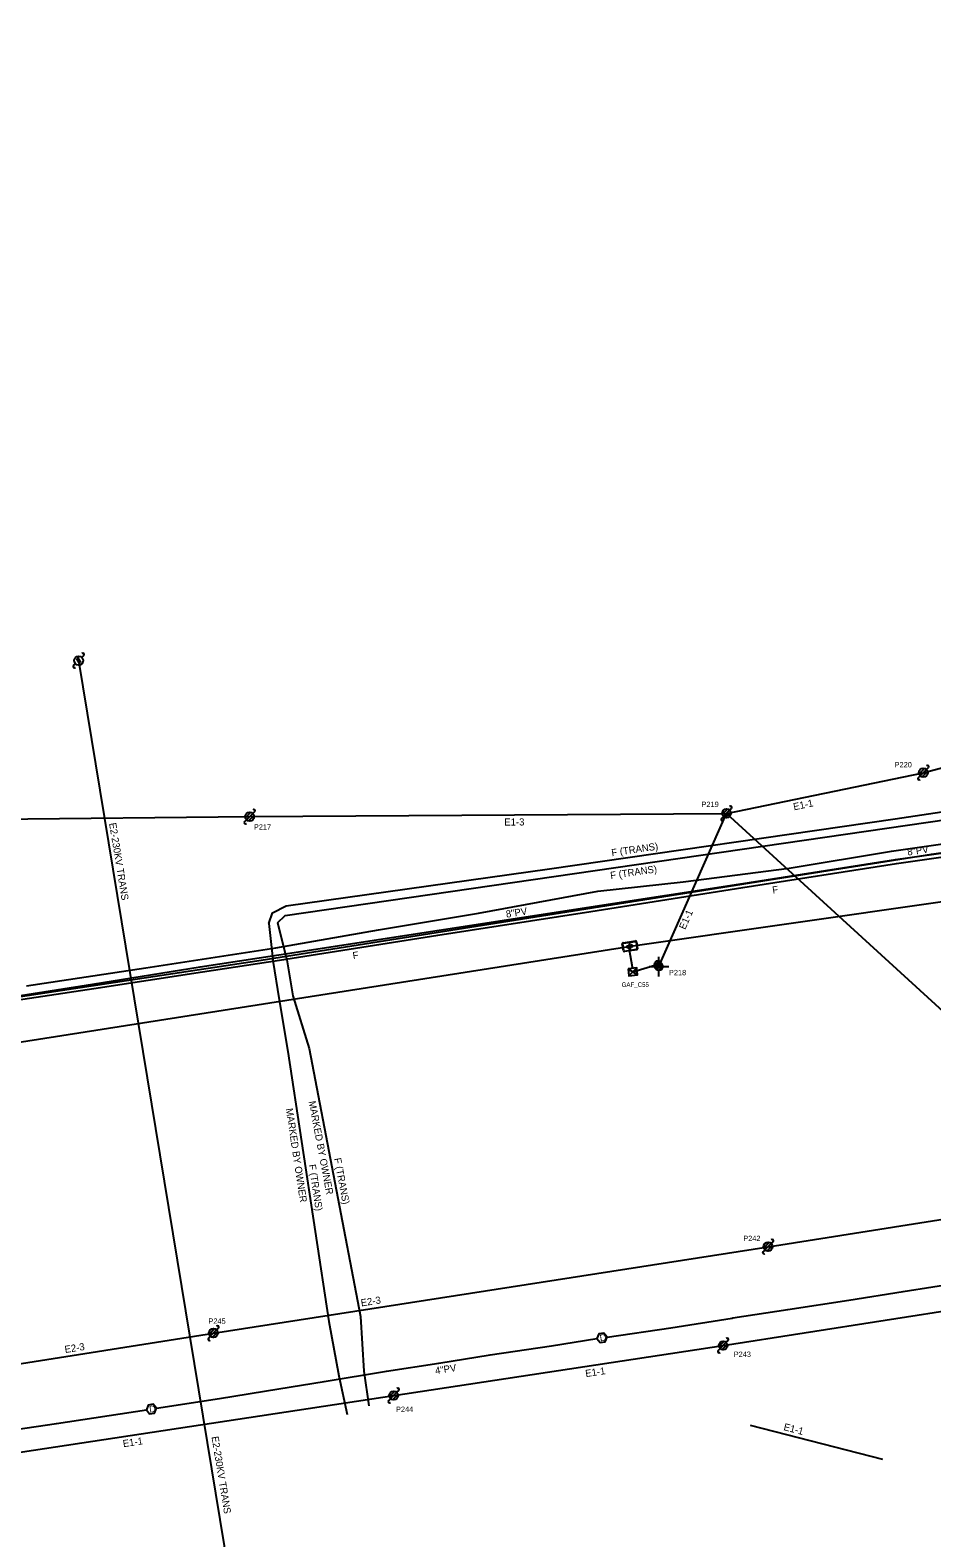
# Model space of a CAD drawing. Extents: x 1614474 to 1865144, y 1098877 to 1212550.
# Drawn here: x 1775781 to 1776287, y 1179752 to 1180599 of the extents above; entities that cross this region are included whole.
import ezdxf

# ---------------------------------------------------------------- set-up
doc = ezdxf.new("R2010")
doc.units = 0
for name, color, linetype in [('BFUSER_CABINET', 7, 'Continuous'), ('BFUSER_DUCTENCLOSURE', 7, 'Continuous'), ('BFUSER_FIBERNODE', 7, 'Continuous'), ('BFUSER_FIBERNODENAME', 7, 'Continuous'), ('BFUSER_FIBERSPAN', 7, 'Continuous'), ('BFUSER_FIBERSPLICEENCLOSURE', 7, 'Continuous'), ('RD_EX_SU_Elec', 7, 'Continuous'), ('RD_EX_SU_H2O', 7, 'Continuous'), ('RD_EX_SU_Ovhd', 7, 'Continuous'), ('RD_EX_SU_Pole', 7, 'Continuous'), ('RD_EX_SU_Telecom', 7, 'Continuous'), ('RD_EX_SU_TX_H2O', 7, 'Continuous'), ('RD_EX_SU_TX_Pole', 7, 'Continuous'), ('RD_EX_SU_TX_Telecom', 7, 'Continuous')]:
    doc.layers.add(name, color=color, linetype=linetype)

# ---------------------------------------------------------------- blocks, each defined once
blk = doc.blocks.new('SUE_PLT')
at = {"layer": 'RD_EX_SU_Elec'}
for p, q in [((1.77, 1.77), (2.83, 2.83)), ((-2.83, -2.83), (-1.77, -1.77))]:
    blk.add_line(p, q, dxfattribs=at)
blk.add_lwpolyline([(-0.49, 1.95), (0.34, -0.06), (-1.12, 0.74), (0.75, -1.95), (0.75, -1.95), (-0.45, 0.15), (0.94, -0.65)], close=True, dxfattribs=at)
blk.add_circle((0, 0), 2.5, dxfattribs=at)
for centre, start, end in [((2.3, 3.36), 315, 135), ((-2.3, -3.36), 135, 315)]:
    blk.add_arc(centre, 0.75, start, end, dxfattribs=at)

msp = doc.modelspace()

# ---------------------------------------------------------------- linework, layer by layer
at = {"layer": 'BFUSER_CABINET'}
for p, q in [((1776116.61, 1180071.7), (1776121.95, 1180068.18)), ((1776121.58, 1180072.16), (1776116.97, 1180067.72))]:
    msp.add_line(p, q, dxfattribs=at)
msp.add_lwpolyline([(1776116.61, 1180071.7), (1776116.97, 1180067.72), (1776121.95, 1180068.18), (1776121.58, 1180072.16)], close=True, dxfattribs=at)
at = {"layer": 'BFUSER_DUCTENCLOSURE'}
msp.add_line((1776117.32, 1180086.55), (1776117.98, 1180082.09), dxfattribs=at)
for points in [[(1776113.98, 1180081.75), (1776113.4, 1180085.71)], [(1776114.19, 1180081.93), (1776113.65, 1180085.6)], [(1776113.82, 1180086.28), (1776120.75, 1180087.3)], [(1776113.99, 1180086.05), (1776120.65, 1180087.04)], [(1776121.1, 1180086.7), (1776121.65, 1180083.03)], [(1776121.31, 1180086.88), (1776121.9, 1180082.92)], [(1776121.48, 1180082.36), (1776114.55, 1180081.33)], [(1776114.65, 1180081.6), (1776121.31, 1180082.58)]]:
    msp.add_lwpolyline(points, dxfattribs=at)
for centre, radius, start, end in [((1776113.89, 1180085.78), 0.5, 98.4061, 188.4061), ((1776114.05, 1180085.66), 0.4, 98.4061, 188.4061), ((1776120.71, 1180086.64), 0.4, 8.4061, 98.4061), ((1776120.82, 1180086.81), 0.5, 8.4061, 98.4061), ((1776114.48, 1180081.83), 0.5, 188.4061, 278.4061), ((1776114.59, 1180081.99), 0.4, 188.4061, 278.4061), ((1776121.25, 1180082.98), 0.4, 278.4061, 8.4061), ((1776121.4, 1180082.85), 0.5, 278.4061, 8.4061)]:
    msp.add_arc(centre, radius, start, end, dxfattribs=at)
at = {"layer": 'BFUSER_FIBERNODE'}
msp.add_line((1776131.53, 1180073.61), (1776135.36, 1180074.75), dxfattribs=at)
msp.add_lwpolyline([(1776132.68, 1180073.95), (1776134.26, 1180074.42), (1776134.46, 1180073.74), (1776132.89, 1180073.27)], close=True, dxfattribs=at)
msp.add_circle((1776133.44, 1180074.18), 2, dxfattribs=at)
msp.add_arc((1776133.52, 1180074.03), 0.992, 230.51607, 342.80602, dxfattribs=at)
at = {"layer": 'BFUSER_FIBERSPAN'}
for p, q in [((1776117.12, 1180083.43), (1776119.12, 1180071.68)), ((1776119.28, 1180069.94), (1776133.47, 1180074.19))]:
    msp.add_line(p, q, dxfattribs=at)
for points in [[(1776119.38, 1180084.52), (1776909.44, 1180197.58), (1777549.89, 1180288.26), (1777793.65, 1180334.21), (1778099.34, 1180399.49), (1778312.74, 1180438.72), (1779456.83, 1180598.99)], [(1772266.13, 1179233.73), (1772993.33, 1179552.36), (1773074.83, 1179562.18), (1773346.25, 1179631.55), (1773610.67, 1179692.14), (1774668.73, 1179856.77), (1776115.67, 1180083.91)]]:
    msp.add_lwpolyline(points, dxfattribs=at)
at = {"layer": 'BFUSER_FIBERSPLICEENCLOSURE'}
for p, q in [((1776115.81, 1180084.23), (1776115.82, 1180084.23)), ((1776115.83, 1180084.1), (1776115.81, 1180084.23)), ((1776115.82, 1180084.25), (1776116.17, 1180084.32)), ((1776115.85, 1180084.09), (1776115.82, 1180084.25)), ((1776115.82, 1180084.23), (1776115.85, 1180084.11)), ((1776116.39, 1180083.43), (1776116.16, 1180084.5)), ((1776116.16, 1180084.47), (1776116.27, 1180084.5)), ((1776116.39, 1180083.44), (1776116.16, 1180084.47)), ((1776116.23, 1180084.65), (1776116.39, 1180084.69)), ((1776116.52, 1180083.35), (1776116.23, 1180084.65)), ((1776116.27, 1180084.5), (1776116.5, 1180083.47)), ((1776116.39, 1180084.69), (1776116.68, 1180083.38)), ((1776116.41, 1180084.58), (1776118.54, 1180085.05)), ((1776116.43, 1180084.52), (1776118.56, 1180084.98)), ((1776116.81, 1180084.76), (1776116.78, 1180084.76)), ((1776116.78, 1180084.76), (1776116.8, 1180084.67)), ((1776116.8, 1180084.67), (1776116.83, 1180084.67)), ((1776116.83, 1180084.67), (1776116.81, 1180084.76)), ((1776117.12, 1180084.83), (1776117.09, 1180084.83)), ((1776117.09, 1180084.83), (1776117.11, 1180084.74)), ((1776117.11, 1180084.74), (1776117.14, 1180084.74)), ((1776117.14, 1180084.74), (1776117.12, 1180084.83)), ((1776117.91, 1180085.01), (1776117.88, 1180085)), ((1776117.88, 1180085), (1776117.9, 1180084.91)), ((1776117.9, 1180084.91), (1776117.93, 1180084.92)), ((1776117.93, 1180084.92), (1776117.91, 1180085.01)), ((1776118.22, 1180085.07), (1776118.19, 1180085.07)), ((1776118.19, 1180085.07), (1776118.21, 1180084.98)), ((1776118.21, 1180084.98), (1776118.24, 1180084.99)), ((1776118.24, 1180084.99), (1776118.22, 1180085.07)), ((1776118.56, 1180084.98), (1776118.58, 1180084.86)), ((1776118.62, 1180085), (1776118.65, 1180084.87)), ((1776118.74, 1180084.82), (1776118.95, 1180084.87)), ((1776118.75, 1180084.75), (1776118.97, 1180084.8)), ((1776118.97, 1180084.8), (1776119.12, 1180084.1)), ((1776119.04, 1180084.81), (1776119.19, 1180084.12)), ((1776115.85, 1180084.11), (1776115.83, 1180084.1)), ((1776116.2, 1180084.17), (1776115.85, 1180084.09)), ((1776115.85, 1180084.01), (1776115.87, 1180084.02)), ((1776115.88, 1180083.89), (1776115.85, 1180084.01)), ((1776115.86, 1180084.03), (1776116.22, 1180084.11)), ((1776115.9, 1180083.88), (1776115.86, 1180084.03)), ((1776115.87, 1180084.02), (1776115.89, 1180083.89)), ((1776115.89, 1180083.89), (1776115.88, 1180083.89)), ((1776115.89, 1180083.82), (1776115.91, 1180083.82)), ((1776115.98, 1180083.43), (1776115.89, 1180083.82)), ((1776116.25, 1180083.95), (1776115.9, 1180083.88)), ((1776115.9, 1180083.84), (1776116.25, 1180083.92)), ((1776116, 1180083.42), (1776115.9, 1180083.84)), ((1776115.91, 1180083.82), (1776115.99, 1180083.44)), ((1776115.99, 1180083.44), (1776115.98, 1180083.43)), ((1776116.35, 1180083.5), (1776116, 1180083.42)), ((1776116.19, 1180084.16), (1776116.2, 1180084.11)), ((1776116.24, 1180083.95), (1776116.38, 1180083.49)), ((1776116.5, 1180083.47), (1776116.39, 1180083.44)), ((1776116.68, 1180083.38), (1776116.52, 1180083.35)), ((1776119.12, 1180084.1), (1776116.64, 1180083.56)), ((1776119.14, 1180084.04), (1776116.66, 1180083.49))]:
    msp.add_line(p, q, dxfattribs=at)
for centre, radius, start, end in [((1776116.16, 1180084.35), 0.0265, 282.42738, 13.11766), ((1776118.56, 1180084.98), 0.0694, 12.42738, 102.42738), ((1776118.72, 1180084.89), 0.139, 192.42738, 282.42738), ((1776118.66, 1180084.63), 0.42, 31.30954, 99.43431), ((1776118.66, 1180084.63), 0.392, 37.4733, 96.38511), ((1776118.72, 1180084.89), 0.0694, 192.42738, 282.42738), ((1776118.97, 1180084.8), 0.0694, 12.37903, 102.42738), ((1776118.35, 1180084.3), 0.857, 344.43794, 37.27065), ((1776116.21, 1180084.14), 0.0265, 11.73711, 102.42738), ((1776116.21, 1180084.14), 0.0265, 282.42738, 13.11766), ((1776116.26, 1180083.93), 0.0265, 11.73711, 102.42738), ((1776116.36, 1180083.47), 0.0265, 11.73711, 102.42738), ((1776119.12, 1180084.1), 0.0694, 282.42738, 12.37903)]:
    msp.add_arc(centre, radius, start, end, dxfattribs=at)
at = {"layer": 'RD_EX_SU_H2O'}
for points in [[(1775079.31, 1179947.86), (1775099.56, 1179951.26), (1775135.1, 1179956.75), (1775200.12, 1179966.22), (1775230.46, 1179971.15), (1775265.28, 1179976.78), (1775296.44, 1179981.42), (1775327.06, 1179986.33), (1775627.47, 1180033.75), (1775910.53, 1180076.48), (1776287.14, 1180136.1), (1776361.29, 1180146.68), (1776578.76, 1180172.75), (1776784.59, 1180199.86), (1777026.8, 1180236.7)], [(1776104.82, 1179864.77), (1776140.68, 1179869.96), (1776175.04, 1179875.44), (1776175.54, 1179875.52), (1776206.34, 1179880.25), (1776240.64, 1179885.5), (1776271.17, 1179890.42), (1776304.63, 1179895.52), (1776336.21, 1179900.32), (1776336.32, 1179900.34)], [(1775851.67, 1179824.72), (1775887.03, 1179830.27), (1775920.48, 1179835.6), (1775945.8, 1179839.86), (1775980.95, 1179845.52), (1776010.25, 1179850.15), (1776039.23, 1179854.67), (1776073.67, 1179859.88), (1776099.12, 1179863.88)], [(1775632.38, 1179793.92), (1775636.25, 1179794.39), (1775650.79, 1179796.27), (1775680.62, 1179800.13), (1775721.45, 1179805.64), (1775756.05, 1179810.32), (1775795.55, 1179816.27), (1775845.96, 1179823.86)]]:
    msp.add_lwpolyline(points, dxfattribs=at)
for points in [[(1776104.82, 1179864.77), (1776103.01, 1179867.02), (1776100.16, 1179866.57), (1776099.12, 1179863.88), (1776100.93, 1179861.63), (1776103.79, 1179862.08)], [(1775851.67, 1179824.72), (1775849.87, 1179826.98), (1775847.02, 1179826.55), (1775845.96, 1179823.86), (1775847.76, 1179821.6), (1775850.62, 1179822.03)]]:
    msp.add_lwpolyline(points, close=True, dxfattribs=at)
at = {"layer": 'RD_EX_SU_Ovhd'}
for p, q in [((1775807.93, 1180244.81), (1775904.8, 1179655.02)), ((1776282.53, 1180181.83), (1776334.27, 1180195.67)), ((1776171.93, 1180158.93), (1776282.53, 1180181.83)), ((1775583.33, 1180154.06), (1775904.05, 1180157.14)), ((1775904.05, 1180157.14), (1776171.93, 1180158.93)), ((1776133.99, 1180072.92), (1776171.93, 1180158.93)), ((1776171.93, 1180158.93), (1776450.84, 1179903.93)), ((1776195.31, 1179915.49), (1776443.07, 1179954.72)), ((1775883.66, 1179866.98), (1776195.31, 1179915.49)), ((1776170.06, 1179860.01), (1776450.84, 1179903.93)), ((1775717.12, 1179840.5), (1775883.66, 1179866.98)), ((1775984.96, 1179831.92), (1776170.06, 1179860.01)), ((1775716.35, 1179791.24), (1775984.96, 1179831.92)), ((1776185.21, 1179815.22), (1776259.66, 1179796.06))]:
    msp.add_line(p, q, dxfattribs=at)
at = {"layer": 'RD_EX_SU_Pole'}
for p, q in [((1776279.7, 1180179.01), (1776280.77, 1180180.07)), ((1776280.12, 1180181.19), (1776283.18, 1180184.25)), ((1776280.77, 1180180.07), (1776284.3, 1180183.6)), ((1776281.89, 1180179.42), (1776284.95, 1180182.48)), ((1776284.3, 1180183.6), (1776285.36, 1180184.66)), ((1776169.51, 1180158.28), (1776172.57, 1180161.34)), ((1776170.16, 1180157.16), (1776173.69, 1180160.7)), ((1776173.69, 1180160.7), (1776174.75, 1180161.76)), ((1775901.23, 1180154.31), (1775902.29, 1180155.37)), ((1775901.64, 1180156.49), (1775904.7, 1180159.55)), ((1775902.29, 1180155.37), (1775905.82, 1180158.91)), ((1775903.41, 1180154.72), (1775906.47, 1180157.79)), ((1775905.82, 1180158.91), (1775906.88, 1180159.97)), ((1776169.1, 1180156.1), (1776170.16, 1180157.16)), ((1776171.28, 1180156.51), (1776174.34, 1180159.57)), ((1776133.99, 1180075.14), (1776133.99, 1180078.45)), ((1776128.47, 1180072.92), (1776131.78, 1180072.92)), ((1776131.78, 1180073.05), (1776133.87, 1180075.13)), ((1776132.03, 1180071.89), (1776135.03, 1180074.88)), ((1776132.68, 1180071.13), (1776135.79, 1180074.22)), ((1776133.69, 1180070.72), (1776136.19, 1180073.21)), ((1776133.99, 1180067.39), (1776133.99, 1180070.7)), ((1776136.21, 1180072.92), (1776139.52, 1180072.92)), ((1776192.89, 1179914.85), (1776195.95, 1179917.91)), ((1776193.54, 1179913.73), (1776197.07, 1179917.26)), ((1776194.66, 1179913.08), (1776197.72, 1179916.14)), ((1776197.07, 1179917.26), (1776198.13, 1179918.32)), ((1776192.48, 1179912.66), (1776193.54, 1179913.73)), ((1775880.83, 1179864.15), (1775881.89, 1179865.22)), ((1775881.24, 1179866.34), (1775884.3, 1179869.4)), ((1775881.89, 1179865.22), (1775885.43, 1179868.75)), ((1775883.01, 1179864.57), (1775886.07, 1179867.63)), ((1775885.43, 1179868.75), (1775886.49, 1179869.81)), ((1776167.23, 1179857.18), (1776168.29, 1179858.25)), ((1776167.64, 1179859.37), (1776170.7, 1179862.43)), ((1776168.29, 1179858.25), (1776171.83, 1179861.78)), ((1776169.41, 1179857.6), (1776172.47, 1179860.66)), ((1776171.83, 1179861.78), (1776172.89, 1179862.84)), ((1775982.13, 1179829.09), (1775983.19, 1179830.15)), ((1775982.54, 1179831.28), (1775985.61, 1179834.34)), ((1775983.19, 1179830.15), (1775986.73, 1179833.69)), ((1775984.31, 1179829.51), (1775987.37, 1179832.57)), ((1775986.73, 1179833.69), (1775987.79, 1179834.75))]:
    msp.add_line(p, q, dxfattribs=at)
for centre, radius in [((1776282.53, 1180181.83), 2.5), ((1776171.93, 1180158.93), 2.5), ((1775904.05, 1180157.14), 2.5), ((1776133.99, 1180072.92), 2.22), ((1776195.31, 1179915.49), 2.5), ((1775883.66, 1179866.98), 2.5), ((1776170.06, 1179860.01), 2.5), ((1775984.96, 1179831.92), 2.5)]:
    msp.add_circle(centre, radius, dxfattribs=at)
for centre, start, end in [((1776284.83, 1180185.19), 315, 135), ((1776280.24, 1180178.48), 135, 315), ((1775906.35, 1180160.5), 315, 135), ((1776174.22, 1180162.29), 315, 135), ((1775901.76, 1180153.78), 135, 315), ((1776169.63, 1180155.57), 135, 315), ((1776197.6, 1179918.85), 315, 135), ((1776193.01, 1179912.13), 135, 315), ((1775881.36, 1179863.62), 135, 315), ((1775885.96, 1179870.34), 315, 135), ((1776172.36, 1179863.37), 315, 135), ((1776167.76, 1179856.65), 135, 315), ((1775987.26, 1179835.28), 315, 135), ((1775982.66, 1179828.56), 135, 315)]:
    msp.add_arc(centre, 0.75, start, end, dxfattribs=at)
at = {"layer": 'RD_EX_SU_Telecom'}
for points in [[(1775914.84, 1180097.06), (1775916.9, 1180103.05), (1775924.57, 1180107.05), (1776072.57, 1180127.73), (1776266.65, 1180155.91), (1776765.03, 1180230.57), (1776769.2, 1180231.88), (1776775.8, 1180316.7), (1776778.02, 1180344.27), (1776786.24, 1180389.18)], [(1775919.62, 1180097.54), (1775923.9, 1180101.6), (1776343.29, 1180162.41), (1776772.57, 1180228.19), (1776777.07, 1180272.08), (1776781.57, 1180342.62), (1776789.82, 1180388.39)], [(1775758.43, 1180054.01), (1775815.79, 1180062.96), (1775876.25, 1180072.8), (1775920.38, 1180079.5), (1776009.46, 1180093.25), (1776095.75, 1180106.51), (1776181.05, 1180119.62), (1776266.98, 1180133.11), (1776340.93, 1180143.41), (1776396.03, 1180151.23), (1776454.93, 1180158.69), (1776536.61, 1180168.91), (1776606.86, 1180176.97), (1776706.17, 1180189.01), (1776754.94, 1180195.79), (1776774.44, 1180198.67), (1776775.99, 1180199.97), (1776775.3, 1180203.06), (1776775.16, 1180208.34)], [(1775758.91, 1180052.04), (1775816.52, 1180060.6), (1775877.51, 1180069.95), (1775920.73, 1180076.58), (1776009.66, 1180090.52), (1776095.73, 1180103.84), (1776181.09, 1180117.29), (1776267.46, 1180130.73), (1776341.05, 1180141.25), (1776396.24, 1180148.92), (1776454.9, 1180156.29), (1776537.33, 1180166.2), (1776606.7, 1180174.18), (1776706.91, 1180186.49), (1776757.57, 1180193.24), (1776761.33, 1180195.25), (1776761.19, 1180199.99), (1776760.62, 1180205.15)], [(1775778.64, 1180062.09), (1775845.67, 1180072.11), (1775918.69, 1180083.41), (1775976.35, 1180093.46), (1776032.52, 1180102.81), (1776099.55, 1180115.18), (1776147.55, 1180120.58), (1776207.07, 1180128.23), (1776264.72, 1180137.79), (1776339.25, 1180148.31), (1776422.82, 1180159.28), (1776508.45, 1180170.28), (1776604.94, 1180179.98), (1776675.52, 1180188.85), (1776733.78, 1180196.49), (1776759.12, 1180200.38), (1776765.61, 1180202.42), (1776770.56, 1180208.08)], [(1775914.84, 1180097.06), (1775917.13, 1180075.09), (1775920.49, 1180055.33), (1775925.51, 1180025.26), (1775948.5, 1179873.43), (1775954.2, 1179843.03), (1775958.84, 1179821.24)], [(1775919.62, 1180097.54), (1775924.89, 1180076.62), (1775928.29, 1180056.45), (1775937.51, 1180026.88), (1775966.33, 1179876.31), (1775968.13, 1179845.58), (1775971.06, 1179826.09)]]:
    msp.add_lwpolyline(points, dxfattribs=at)

# ---------------------------------------------------------------- block references
at = {"layer": 'RD_EX_SU_Elec'}
msp.add_blockref('SUE_PLT', (1775807.93, 1180244.81), dxfattribs=at)

# ---------------------------------------------------------------- texts
at = {"layer": 'BFUSER_FIBERNODENAME'}
msp.add_text('GAF_C55', height=2.5, rotation=0.00021, dxfattribs=at).set_placement((1776113, 1180061.49))
at = {"layer": 'RD_EX_SU_H2O'}
for rotation, p in [(8.93669, (1776101.02, 1179862.28)), (8.56218, (1775847.86, 1179822.25))]:
    msp.add_text('D', height=3.75, rotation=rotation, dxfattribs=at).set_placement(p)
at = {"layer": 'RD_EX_SU_Ovhd'}
for s, rotation, p in [('E1-1', 11.7003, (1776209.89, 1180160.66)), ('E2-230KV TRANS', 279.32706, (1775825.01, 1180153.35)), ('E1-3', 0.38257, (1776047.09, 1180152.09)), ('E1-1', 66.20123, (1776148.71, 1180093.36)), ('E2-3', 8.84742, (1775966.77, 1179881.94)), ('E2-3', 9.0364, (1775800.37, 1179855.76)), ('E1-1', 8.62933, (1776092.92, 1179842.24)), ('E1-1', 345.56403, (1776203.72, 1179812.52)), ('E1-1', 8.61243, (1775833.06, 1179802.85)), ('E2-230KV TRANS', 279.32706, (1775882.56, 1179808.67))]:
    msp.add_text(s, height=4, rotation=rotation, dxfattribs=at).set_placement(p)
at = {"layer": 'RD_EX_SU_TX_H2O'}
for s, rotation, p in [('8"PV', 8.12196, (1776273.79, 1180135.26)), ('8"PV', 8.99519, (1776048.32, 1180100.32)), ('4"PV', 8.86302, (1776008.5, 1179843.8))]:
    msp.add_text(s, height=4, rotation=rotation, dxfattribs=at).set_placement(p)
at = {"layer": 'RD_EX_SU_TX_Pole'}
for s, p in [('P220', (1776266.4, 1180184.8)), ('P219', (1776157.9, 1180162.54)), ('P217', (1775906.4, 1180149.82)), ('P218', (1776139.61, 1180068.03)), ('P242', (1776181.36, 1179918.68)), ('P245', (1775880.86, 1179872.2)), ('P243', (1776175.99, 1179853.59)), ('P244', (1775986.23, 1179822.68))]:
    msp.add_text(s, height=3, dxfattribs=at).set_placement(p)
at = {"layer": 'RD_EX_SU_TX_Telecom'}
for s, rotation, p in [('F (TRANS)', 8.2614, (1776107.57, 1180134.83)), ('F (TRANS)', 8.24979, (1776106.92, 1180122.07)), ('F', 8.84965, (1776198.01, 1180113.85)), ('F', 8.90928, (1775962.2, 1180077.01)), ('MARKED BY OWNER', 278.61092, (1775924.32, 1179993)), ('MARKED BY OWNER', 280.8338, (1775937.12, 1179997.01)), ('F (TRANS)', 278.61092, (1775937.19, 1179961.5)), ('F (TRANS)', 280.8338, (1775951.38, 1179965.02))]:
    msp.add_text(s, height=4, rotation=rotation, dxfattribs=at).set_placement(p)

doc.saveas('drawing.dxf')
